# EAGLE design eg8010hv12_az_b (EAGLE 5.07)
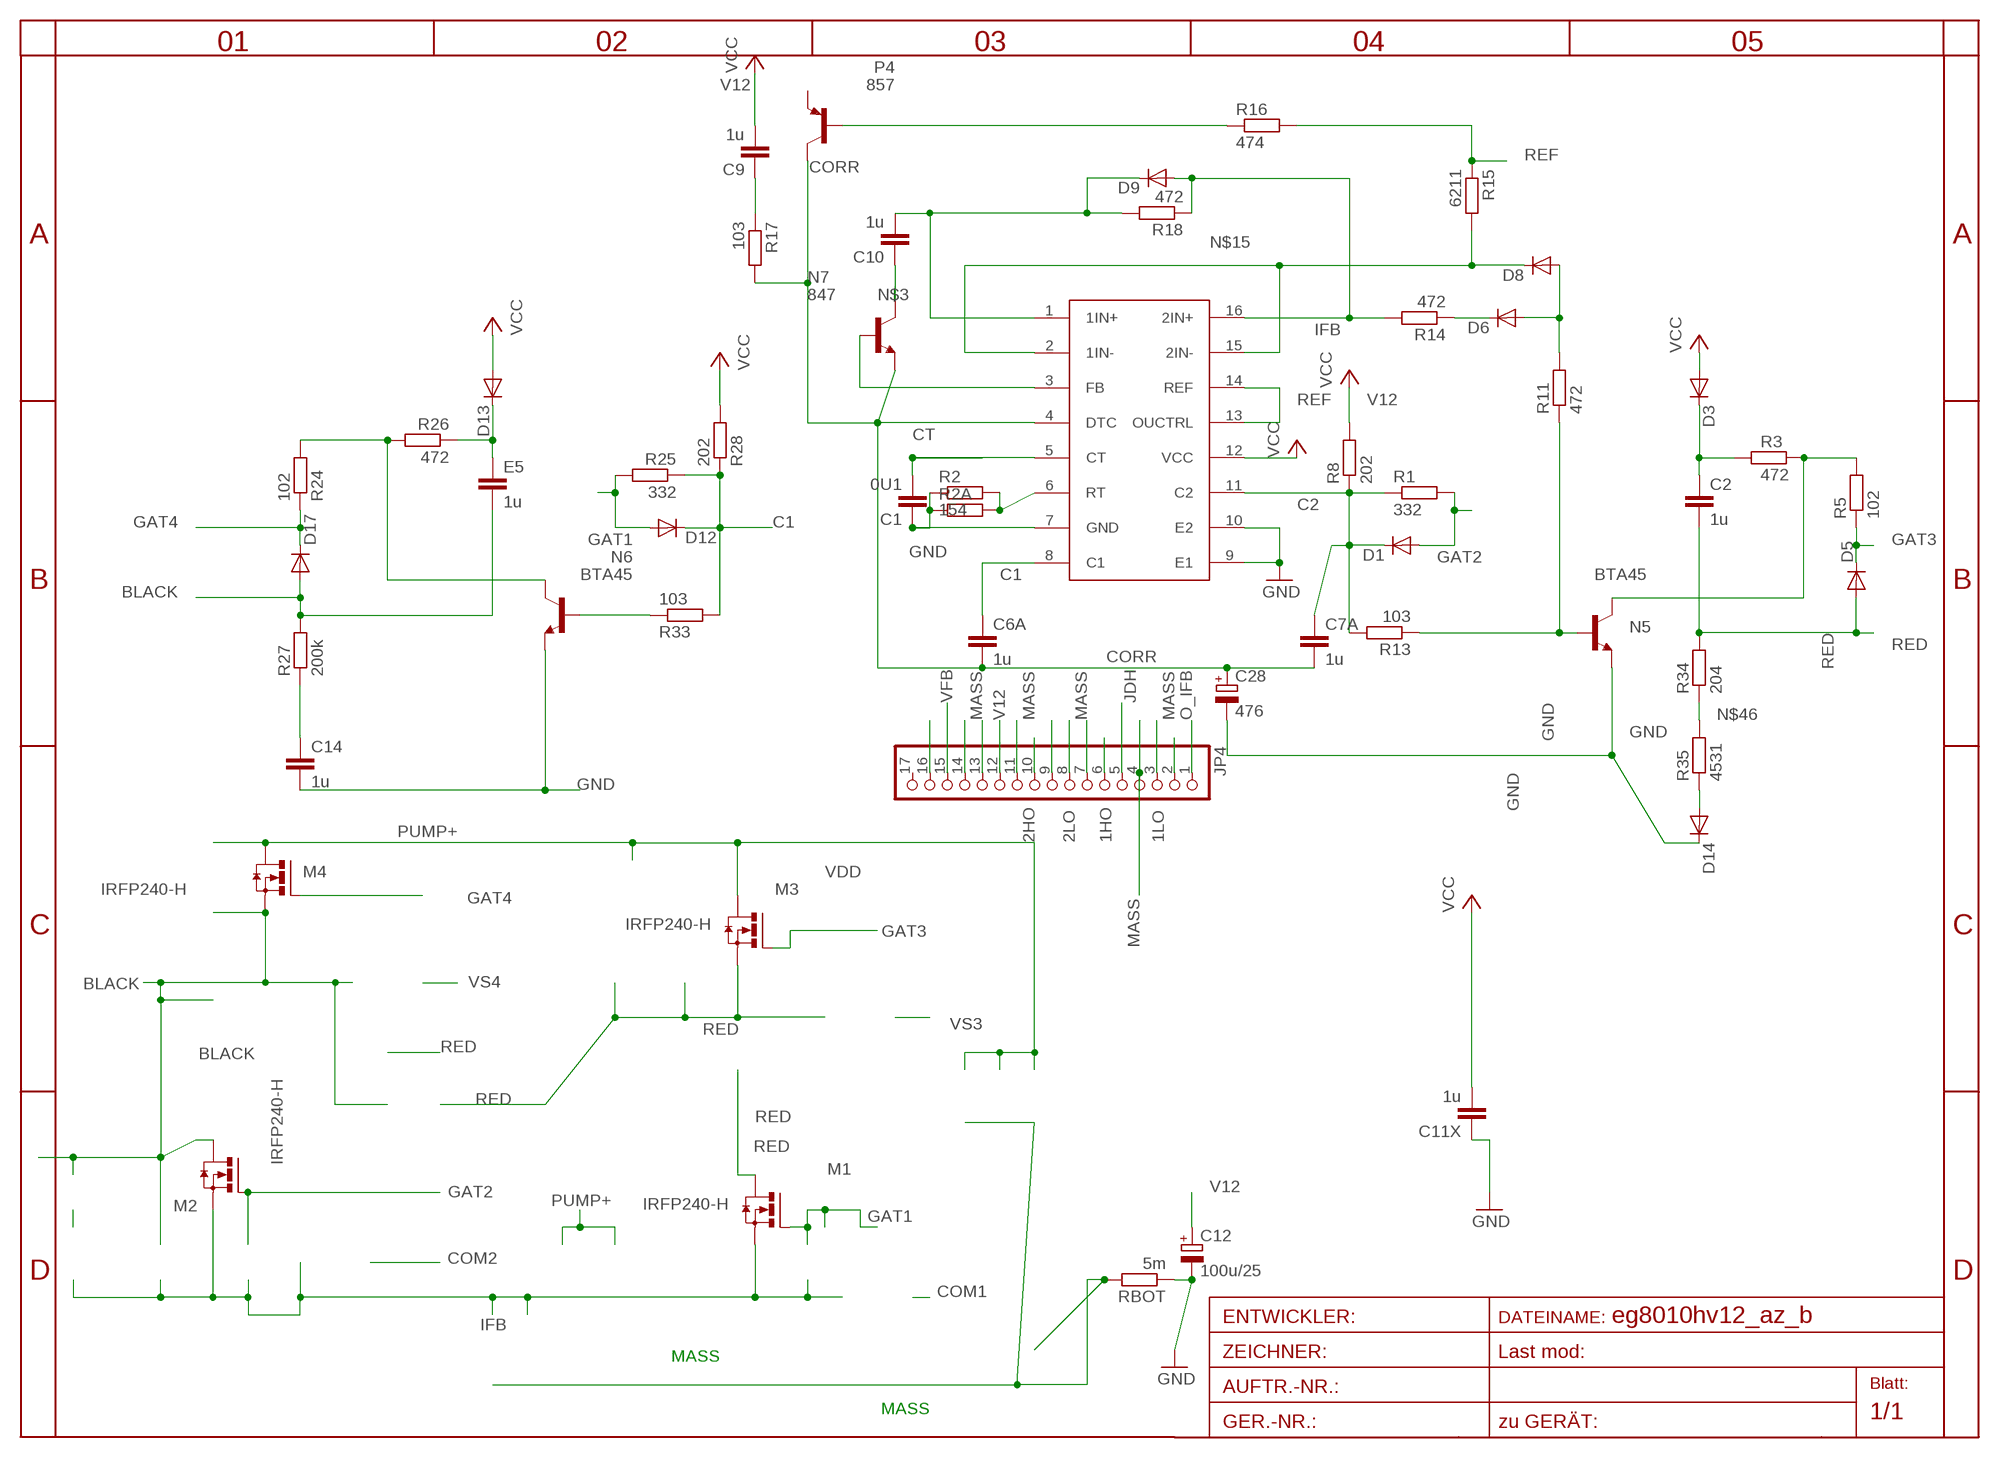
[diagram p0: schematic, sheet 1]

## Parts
7500  AZ7500SO16  [SO16]
C1  0U1  C-EUC0805  [C0805]
C2  1u  C-EUC1206  [C1206]
C6A  1u  C-EUC0805  [C0805]
C7A  1u  C-EUC0805  [C0805]
C9  1u  C-EUC0805  [C0805]
C10  1u  C-EUC1206  [C1206]
C11X  1u  C-EUC1206  [C1206]
C12  100u/25  CPOL-EUD  [PANASONIC_D]
C14  1u  C-EUC1206  [C1206]
C28  476  CPOL-EUD  [PANASONIC_D]
D1  DIODE-MINIMELF  [MINIMELF]
D3  DIODE-SMA-DO214  [SMA-DO214AC]
D5  DIODE-MINIMELF  [MINIMELF]
D6  DIODE-MINIMELF  [MINIMELF]
D8  DIODE-MINIMELF  [MINIMELF]
D9  DIODE-MINIMELF  [MINIMELF]
D12  DIODE-MINIMELF  [MINIMELF]
D13  DIODE-SMA-DO214  [SMA-DO214AC]
D14  DIODE-MINIMELF  [MINIMELF]
D17  DIODE-MINIMELF  [MINIMELF]
E5  1u  C-EUC1206  [C1206]
JP4  PINHD-1X17  [1X17]
M1  IRFP240-H  [TO247BH]
M2  IRFP240-H  [TO247BH]
M3  IRFP240-H  [TO247BH]
M4  IRFP240-H  [TO247BH]
N5  BTA45  SMBTA45HV  [SOT23HV]
N6  BTA45  SMBTA45HV  [SOT23HV]
N7  847  BC847ALT1SMD  [SOT23]
P4  857  BC857ALT1SMD  [SOT23-BEC]
R1  332  R-EU_R0805  [R0805]
R2  154  R-EU_R0805  [R0805]
R2A  R-EU_R0805  [R0805]
R3  472  R-EU_R0805  [R0805]
R5  102  R-EU_R1206  [R1206]
R8  202  R-EU_R0805  [R0805]
R11  472  R-EU_R0805  [R0805]
R13  103  R-EU_R0805  [R0805]
R14  472  R-EU_R0805  [R0805]
R15  6211  R-EU_R1206  [R1206]
R16  474  R-EU_R1206  [R1206]
R17  103  R-EU_R1206  [R1206]
R18  472  R-EU_R0805  [R0805]
R24  102  R-EU_R1206  [R1206]
R25  332  R-EU_R0805  [R0805]
R26  472  R-EU_R0805  [R0805]
R27  200k  R-EU_R1206  [R1206]
R28  202  R-EU_R0805  [R0805]
R33  103  R-EU_R0805  [R0805]
R34  204  R-EU_R0805  [R0805]
R35  4531  R-EU_R0805  [R0805]
RBOT  5m  R-EU_0204/5  [0204/5]

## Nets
1HO: JP4.6
1LO: JP4.3
2HO: JP4.10
2LO: JP4.8
BLACK: D17.A E5.2 M2.D M4.S R27.2
C1: 7500.8(C1) C6A.1 D12.C R25.1 R28.1 R33.2
C2: 7500.11(C2) C7A.1 D1.C R1.1 R8.1 R13.2
CORR: 7500.4(DTC) C6A.2 C7A.2 C28.+ N7.2(E) P4.C R17.2
CT: 7500.5(CT) C1.2
DFG1: JP4.9
GAT1: D12.A M1.G R25.2
GAT2: D1.A M2.G R1.2
GAT3: D5.C M3.G R5.1
GAT4: D17.C M4.G R24.1
GND: 7500.7(GND) 7500.9(E1) 7500.10(E2) C1.1 C11X.1 C12.- C14.2 C28.- D14.C N5.2(E) N6.2(E) R2.1 R2A.1 RBOT.1
IFB: 7500.16(2IN+) D9.A M1.S M2.S R14.2 R18.1
JDH: JP4.5
MASS: JP4.2 JP4.4 JP4.7 JP4.11 JP4.13 RBOT.2
N$3: 7500.1(1IN+) C10.2 D9.C R18.2
N$4: C2.1 D3.K(C) R3.1
N$5: N5.3(C) R3.2 R5.2
N$11: N5.1(B) R11.1 R13.1
N$13: D6.A D8.A R11.2
N$15: 7500.2(1IN-) 7500.15(2IN-) D8.C R15.2
N$36: D6.C R14.1
N$37: P4.B R16.1
N$38: 7500.6(RT) R2.2 R2A.2
N$39: C9.1 R17.1
N$40: 7500.3(FB) N7.1(B)
N$41: C10.1 N7.3(C)
N$42: D13.K(C) E5.1 R26.1
N$43: N6.3(C) R24.2 R26.2
N$44: N6.1(B) R33.1
N$45: C14.1 R27.1
N$46: R34.1 R35.2
N$47: D14.A R35.1
O_IFB: JP4.1
PUMP+: M3.D M4.D
RED: C2.2 D5.A M1.D M3.S R34.2
REF: 7500.13(OUCTRL) 7500.14(REF) R15.1 R16.2
TFB: JP4.16
V12: 7500.12(VCC) C9.2 C11X.2 C12.+ D3.A D13.A JP4.12 R8.2 R28.2 ; supply symbol labelled VCC
VDD: JP4.14
VFB: JP4.15
Unconnected: JP4.17 P4.E

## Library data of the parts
7500 = az7500:AZ7500
C1 C2 C6A C7A C9 C10 C11X C14 E5 = rcl:C-EU: CAPACITOR, European symbol
C12 C28 = rcl:CPOL-EU: POLARIZED CAPACITOR, European symbol
D1 D3 D5 D6 D8 D9 D12-D14 D17 = diode:DIODE-: DIODE
JP4 = pinhead:PINHD-1X17: PIN HEADER
M1-M4 = transistor-power:IRFP240: HEXFET Power MosFet Source: http://www.irf.com/
N5 N6 = transistor-npn:SMBTA45
N7 = transistor-npn:BC847*: NPN Transistor
P4 = transistor-pnp:BC857*: PNP Transistror
R1 R2 R2A R3 R5 R8 R11 R13-R18 R24-R28 R33-R35 RBOT = rcl:R-EU_: RESISTOR, European symbol

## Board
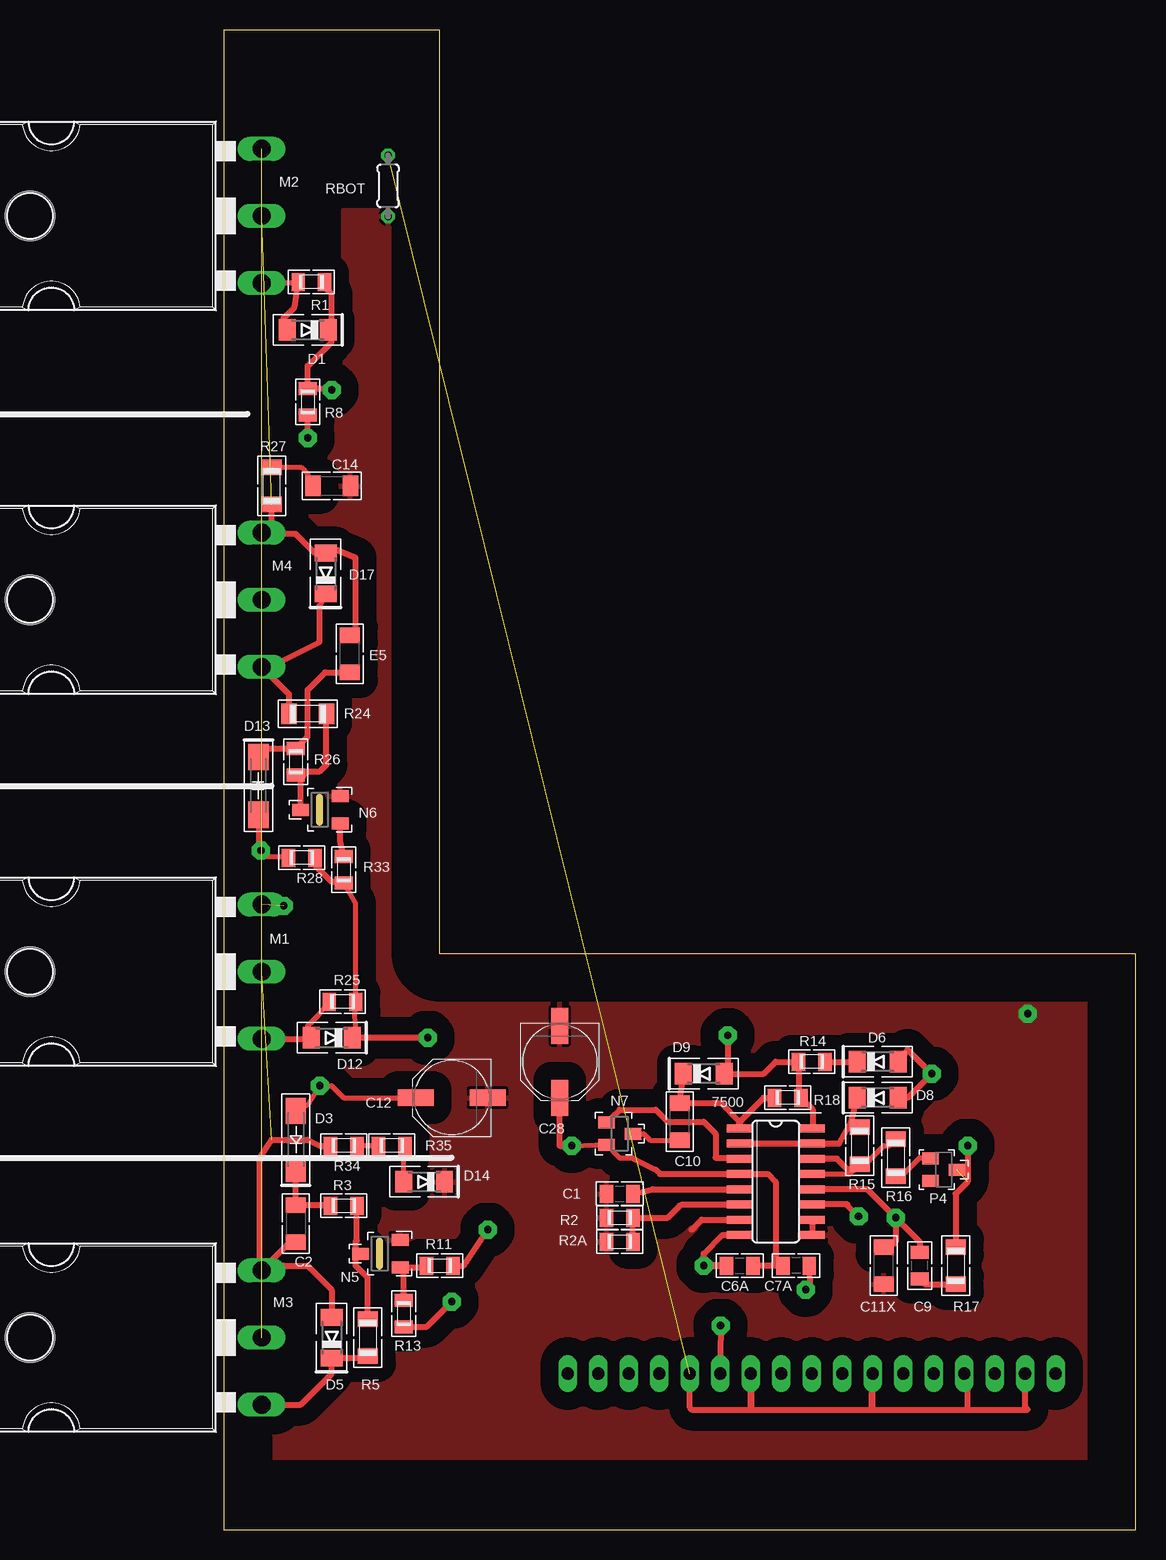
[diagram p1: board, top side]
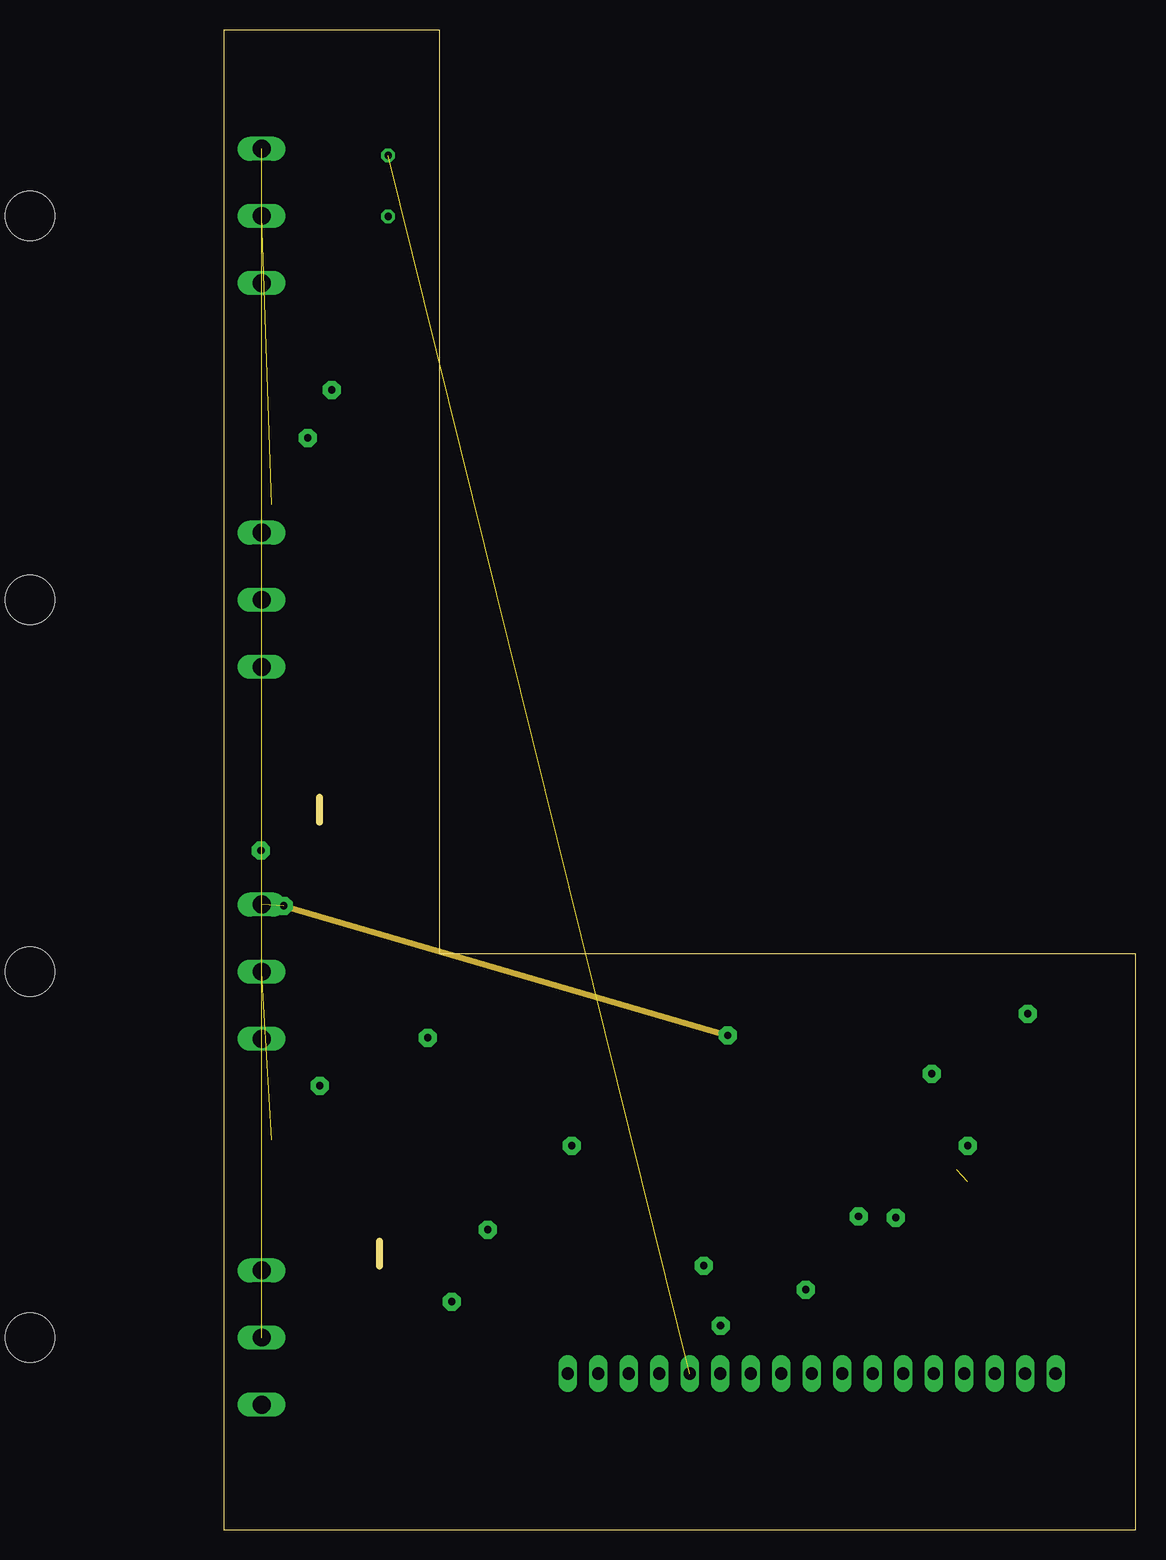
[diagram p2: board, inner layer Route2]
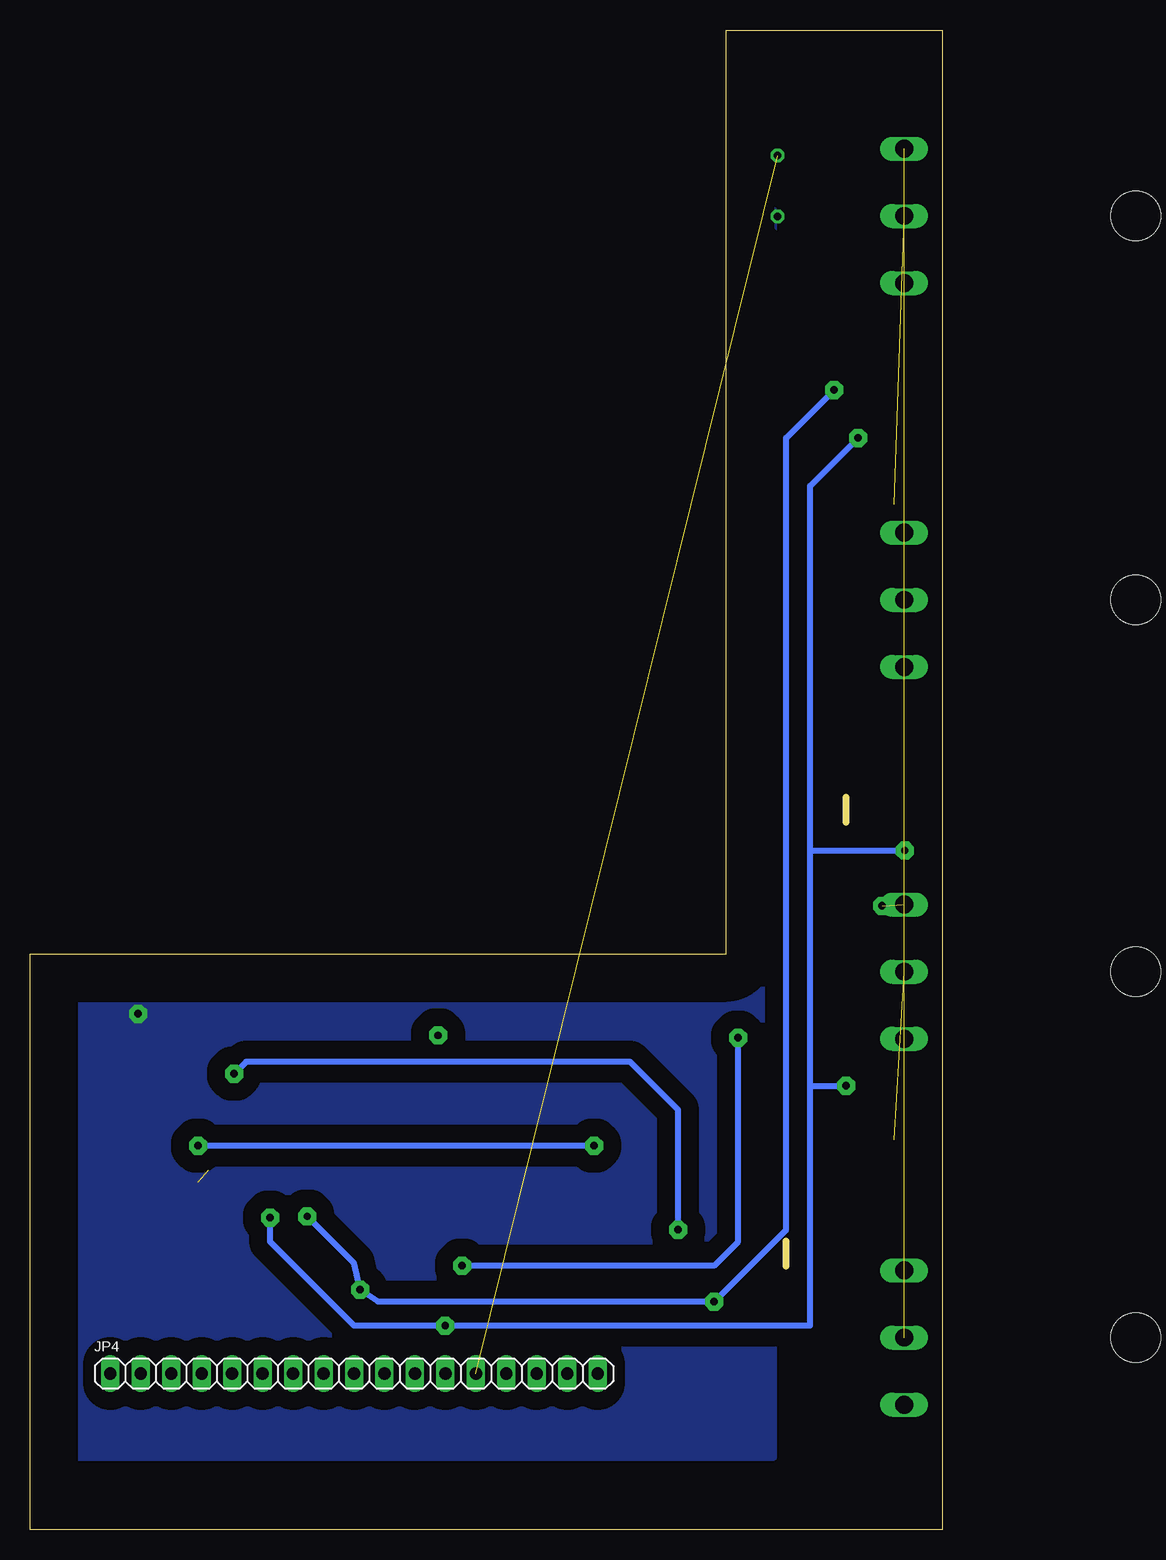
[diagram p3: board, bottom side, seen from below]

Size 76 x 125 mm. Coordinates in mm from the lower left corner, seen from the top.
Outline: 0,0 76,0 76,48 18,48 18,125 0,125 0,0
Copper layers (1*16): Top 0.035mm / dielectric 1.5mm / Bottom 0.035mm
Design rules "default *": minimum track width 10mil, minimum drill 20mil, track to track 8mil, track to pad 8mil, pad to pad 8mil, via to via 8mil, smd to smd 8mil, copper to edge 4mm, drill to drill 8mil, minimum pad ring 10mil, minimum via ring 8mil, stop-mask expansion 4mil, vias tented up to drill 0mil, thermal gap 10mil

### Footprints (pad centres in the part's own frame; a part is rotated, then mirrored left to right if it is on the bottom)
SO16 = smd 2.032 x 0.66: 1 -3.073,4.445; 2 -3.073,3.175; 3 -3.073,1.905; 4 -3.073,0.635; 5 -3.073,-0.635; 6 -3.073,-1.905; 7 -3.073,-3.175; 8 -3.073,-4.445; 9 3.073,-4.445; 10 3.073,-3.175; 11 3.073,-1.905; 12 3.073,-0.635; 13 3.073,0.635; 14 3.073,1.905; 15 3.073,3.175; 16 3.073,4.445
C0805 = smd 1.1 x 1.5: 1 -1.1,0; 2 1.1,0
C1206 = smd 1.3 x 1.7: 1 -1.55,0; 2 1.55,0
PANASONIC_D = smd 3 x 1.4: + 3,0; - -3,0
MINIMELF = smd 1.4 x 1.8: A 1.7,0; C -1.7,0
SMA-DO214AC = smd 2.2 x 1.7: A 2.4,0; K -2.4,0
1X17 = drill 1.016 long: 1 -20.32,0; 2 -17.78,0; 3 -15.24,0; 4 -12.7,0; 5 -10.16,0; 6 -7.62,0; 7 -5.08,0; 8 -2.54,0; 9 0,0; 10 2.54,0; 11 5.08,0; 12 7.62,0; 13 10.16,0; 14 12.7,0; 15 15.24,0; 16 17.78,0; 17 20.32,0
TO247BH = drill 1.499 long: D 0,-10.16; G -5.588,-10.16; S 5.588,-10.16 | hole 4.115: 0,9.144
SOT23HV = smd 1 x 1.4: 1 -1.15,-1.7; 2 1.15,-1.7; 3 0,1.6
SOT23 = smd 1 x 1.4: 1 -0.95,-1.1; 2 0.95,-1.1; 3 0,1.1
SOT23-BEC = smd 1 x 1.4: B -0.95,-1.1; C 0,1.1; E 0.95,-1.1
R0805 = smd 1.1 x 1.5: 1 -1.1,0; 2 1.1,0
R1206 = smd 1.3 x 1.7: 1 -1.55,0; 2 1.55,0
0204/5 = drill 0.6 octagon: 1 -2.54,0; 2 2.54,0

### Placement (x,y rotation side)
7500  46,29 0 top
C1  33,28 0 top
C2  6,25.5 270 top
C6A  43,22 0 top
C7A  47.7,22 180 top
C9  58,22 90 top
C10  38,34 90 top
C11X  55,22 90 top
C12  19,36 180 top
C14  9,87 0 top
C28  28,39 270 top
D1  7,100 180 top
D3  6,32.5 90 top
D5  9,16 90 top
D6  54.5,39 0 top
D8  54.5,36 0 top
D9  40,38 0 top
D12  9,41 180 top
D13  2.9,62 270 top
D14  16.7,29 180 top
D17  8.5,79.7 90 top
E5  10.5,73 90 top
JP4  49,13 0 bottom
M1  -7,46.5 90 top
M2  -7,109.5 90 top
M3  -7,16 90 top
M4  -7,77.5 90 top
N5  13,23 90 top
N6  8,60 90 top
N7  33,33 270 top
P4  60,30 270 top
R1  7.3,104 180 top
R2  33,26 0 top
R2A  33,24 0 top
R3  10,27 0 top
R5  12,16 90 top
R8  7,94 270 top
R11  18,22 0 top
R13  15,18 270 top
R14  49,39 180 top
R15  53,32 90 top
R16  56,31 90 top
R17  61,22 90 top
R18  47,36 180 top
R24  7,68 0 top
R25  9.9,44 180 top
R26  6,64 270 top
R27  4,87 270 top
R28  6.5,56 180 top
R33  10,55 270 top
R34  10,32 180 top
R35  14,32 180 top
RBOT  13.7,112 90 top

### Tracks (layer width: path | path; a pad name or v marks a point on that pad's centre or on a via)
BLACK  (1 unrouted)
  Top 0.5: R27.2 4,83.93 3.54,83.46 | 3.54,83.46 M4.S 3.07,83 | E5.2 10.45,74.5 11,74.5 11,81 9.3,81.7 D17.A 7.6,81.4 6,83 4,83 3.54,83.46
C1  (via drill 0.6 pad 1.5)
  Top 0.406: R33.2 11,52.2 R25.1 10.9,42.8 11,42 11,41.3 D12.C
  Top 0.5: 7500.8 41.56,24.55 40,23 40,22.1 C6A.1 v40,22 | v17,41 D12.C | R28.1 7.6,55.4 9,54 9.9,54 R33.2
  Bottom 0.5: v17,41 17,24 19,22 v40,22
C2  (via drill 0.6 pad 1.5)
  Top 0.5: R1.1 8.1,103.9 9,103 9,100.3 D1.C 9,99.7 9,99 7,97 R8.1 7.9,95.1 v9,95 | R13.2 16.9,16.9 v19,19 | v52.91,26.09 52,27 52,27.09 7500.11 | v48.5,20 48.9,20 C7A.1
  Bottom 0.5: v9,95 13,91 13,25 v19,19 47,19 v48.5,20 49,22.19 v52.91,26.09
CORR  (via drill 0.6 pad 1.5)  (1 unrouted)
  Top 0.406: v29,32 31,32.05 N7.2 32.95,31 34,31
  Top 0.5: 34,31 36,30 36.36,29.64 7500.4 45.37,29.64 46,29 46,22.1 C7A.2 C6A.2 | v29,32 28,32 C28.+ | P4.C 61.1,30.1 | R17.2 61,28 62,29 v62,32
  Bottom 0.5: v29,32 v62,32
CT
  Top 0.5: 7500.5 35.73,28.36 C1.2
GAT1
  Top 0.406: R25.2 7.9,42.9 7,42 7,41.3 D12.A
  Top 0.5: M1.G 7.21,40.91 D12.A
GAT2
  Top 0.406: M2.G 5.9,103.91 R1.2
  Top 0.5: R1.2 5.9,101.9 5,101 5,100.3 D1.A
GAT3
  Top 0.5: M3.G 6.41,10.41 9,13 D5.C 11.85,14.3 R5.1
GAT4
  Top 0.5: D17.C 8,77 8,74 4,72 3.25,72 M4.G 5.45,69.62 R24.1
GND  (via drill 0.6 pad 1.5)
  Top 0.5: 7500.7 39.83,25.82 39,25 | 7500.9 7500.10
  other vias: 67,43
  pour Top (isolate 1.5): 4,105 10,105 10,110 16,110 16,48 74,48 74,6 4,6
  pour Bottom (isolate 1.5): 14,110 16,110 16,48 74,48 74,6 14,6
IFB  (via drill 0.6 pad 1.5)  (2 unrouted)
  Top 0.5: 7500.16 49.07,35.03 R18.1 47.9,36.2 R14.2 46,39 45,38 D9.A 42,38 v42,41.2
  Route2 0.5: v5,52 v42,41.2
MASS  (1 unrouted)
  Top 0.5: JP4.13 38.84,10.16 39,10 44,10 | 44,10 44,12.92 JP4.11 43.92,10.08 44,10 | 44,10 54,10 | 54,10 54,12.92 JP4.7 54.08,10.08 54,10 | 54,10 62,10 | 62,10 62,12.7 JP4.4 | JP4.2 66.78,10.22 67,10 62,10
N$3
  Top 0.5: D9.C 38.3,37.8 C10.2 41.45,35.55 43,34 | 7500.1 42.93,33.83 43.05,33.95 43,34 | R18.2 45,36 43,34
N$4
  Top 0.406: 8.9,27.05 R3.1
  Top 0.5: D3.K C2.1 8.9,27.05
N$5
  Top 0.5: R5.2 12,21 11,22 11,22.6 N5.3 11,23.4 11,24 11.1,24.1 R3.2
N$11
  Top 0.5: R13.1 15,21.55 N5.1 16.75,21.85 R11.1
N$13  (via drill 0.6 pad 1.5)
  Top 0.5: R11.2 20,22 v22,25 | D8.A 57,36 v59,38 57,40 D6.A
  Bottom 0.5: v22,25 22,35 26,39 58,39 v59,38
N$15
  Top 0.5: 7500.2 7500.15 51.28,32.17 52.28,33.98 | 52.28,33.98 D8.C | R15.2 52.7,33.55 52.28,33.98
N$36
  Top 0.5: R14.1 D6.C
N$37
  Top 0.406: R16.1 56.45,29.45 58,31 58.85,31 P4.B 58.95,30.95 59,31
N$38
  Top 0.5: 7500.6 38.19,27.09 38,27 37,26 R2.2 R2A.2
N$39
  Top 0.5: R17.1 58.45,20.45 C9.1
N$40
  Top 0.5: N7.1 33,34.95 33,35 36,35 37,34 40,34 41,33 41,31 42.83,31 7500.3
N$41
  Top 0.406: C10.1 35.55,32.45 35,33 N7.3
N$42
  Top 0.5: D13.K 3,65 3.1,65.1 R26.1 7,66.1 7,70 8.45,71.45 E5.1
N$43
  Top 0.5: N6.3 6.4,62.5 | 6.4,62.5 R26.2 | R24.2 8.55,63.75 8,63.2 6.9,63.2 6.4,62.5
N$44
  Top 0.5: N6.1 9.7,57.4 R33.1
N$45
  Top 0.406: R27.1 6.45,88.55 7,88 7,87.45 C14.1
N$46
  Top 0.406: R35.2 R34.1
N$47
  Top 0.406: D14.A 15,31.9 R35.1
PUMP+  (1 unrouted)
RED  (1 unrouted)
  Top 0.406: M3.S 3.16,22.16 7,22
  Top 0.5: D5.A 9,20 7,22 3.57,22 M3.S 5.52,23.95 C2.2 | R34.2 8,32 7,32.5 4,32.5 3,31 3,22.32 3.16,22.16
REF
  Top 0.406: 7500.13 52.19,29.64 R15.1 53.45,30.45 55,32 55.45,32 R16.2
  Top 0.5: 7500.14 51.09,30.91 52,30 52.55,30 R15.1
V12  (via drill 0.6 pad 1.5)
  Top 0.406: C12.+ 10,36 9,37 v8,37 7,35.4 D3.A | 4.9,56.1 3.6,56.1 v3.1,56.6 2.9,56.8 D13.A
  Top 0.5: JP4.12 41.38,14.62 v41.4,17 | v7,91 R8.2 | 7500.12 53.63,28.36 v56,26 | 4.9,56.1 R28.2 | C11X.2 55.55,23.55 56,24 v56,26 | C9.2 58,24 v56,26
  Bottom 0.5: 11,37 11,17 v41.4,17 49,17 56,24 v56,26 | 11,56.6 11,87 v7,91 | 11,37 v8,37 | 11,37 11,56.6 | 11,56.6 v3.1,56.6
